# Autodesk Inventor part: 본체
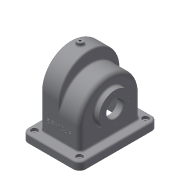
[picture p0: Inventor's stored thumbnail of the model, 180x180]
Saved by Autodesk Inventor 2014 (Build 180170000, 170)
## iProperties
Created: 2017-11
Part Number: 본체
Material: Generic
Document SubType Name: Modeling
Designer: user
Density: 1 g/cm^3
Appearance: Default
Author: user
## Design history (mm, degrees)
sketch "스케치1"
  geometry: L1 (55, -75)-(-55, -75); L2 (-55, -75)-(-55, 75); L3 (-55, 75)-(55, 75); L4 (55, 75)-(55, -75); L5 (55, -75)-(-55, 75); L6 (-55, -75)-(55, 75); 1 further point
  constraints: 12 end point, 2 midpoint, 2 parallel, 1 horizontal, 1 perpendicular
  dimensions: "d0" = 110 distance of L1.start L1.end; "d1" = 150 distance of L1.end L2.end
extrude "돌출1" new body sketch "스케치1" distance "d2" = 15; taper "d3" = 0 deg
sketch "스케치2"
  geometry: L1 (-55, 15)-(55, 15) reference; L2 (-38, 15)-(-38, 138); L3 (-38, 138)-(0, 138); L4 (0, 138)-(0, 115); L5 (0, 115)-(38, 115); L6 (38, 115)-(38, 15); L7 (-55, 0)-(-55, 15) reference; L8 (-38, 15)-(38, 15); L9 (-5, 133)-(-33, 133); L10 (-33, 133)-(-33, 15); L11 (33, 15)-(33, 110); L12 (33, 110)-(-5, 110); L13 (-5, 110)-(-5, 133); 1 further point
  constraints: 22 end point, 4 parallel, 4 perpendicular, 4 point on line, 1 collinear, 1 other
  dimensions: "d4" = 76 horizontal distance of L5.end L2.end; "d5" = 38 distance of L2.end L3.end; "d6" = 55 distance from line of L3.end L7; "d13" = 5 distance between parallel lines of L3 L9; "d102" = 123 distance of L2.end L2.start; "d103" = 100 distance of L5.end L6.end
extrude "돌출2" new body sketch "스케치2" stored distance "d7" = 116; taper "d8" = 0 deg
fillet "모깎기1" dims "d9" = 58
fillet "모깎기2" dims "d10" = 58
fillet "모깎기3" dims "d11" = 3
fillet "모깎기4" dims "d12" = 8
feature "쉘1" dims "d14" = 2
sketch "스케치6"
  geometry: L1 (-30, 56)-(30, 56) reference; L2 (36, 50)-(36, -50) reference; L3 (-36, -50)-(-36, 50) reference; L4 (30, -56)-(-30, -56) reference; A1 r 6 centre (30, 50) between (36, 50) and (30, 56) reference; A2 r 6 centre (-30, 50) between (-30, 56) and (-36, 50) reference; A3 r 6 centre (-30, -50) between (-36, -50) and (-30, -56) reference; A4 r 6 centre (30, -50) between (30, -56) and (36, -50) reference; 1 further point
extrude "돌출3" cut sketch "스케치6" distance "d15" = 15; taper "d16" = 0 deg
fillet "모깎기5" dims "d17" = 12
hole "구멍1" diameter "d20" = 5; stored, may be unused: countersink angle "d24" = 90 deg, drill point angle "d26" = 0 deg; dims "d18" = 10, "d19" = 10, "d21" = 6, "d22" = 12, "d23" = 5, "d25" = 8
hole "구멍2" diameter "d29" = 5; stored, may be unused: countersink angle "d33" = 90 deg, drill point angle "d35" = 0 deg; dims "d27" = 10, "d28" = 10, "d30" = 6, "d31" = 12, "d32" = 5, "d34" = 8
hole "구멍3" diameter "d38" = 5; stored, may be unused: countersink angle "d42" = 90 deg, drill point angle "d44" = 0 deg; dims "d36" = 10, "d37" = 10, "d39" = 6, "d40" = 12, "d41" = 5, "d43" = 8
hole "구멍4" diameter "d47" = 5; stored, may be unused: countersink angle "d51" = 90 deg, drill point angle "d53" = 0 deg; dims "d45" = 10, "d46" = 10, "d48" = 6, "d49" = 12, "d50" = 5, "d52" = 8
fillet "모깎기6" dims "d54" = 3
sketch "스케치8"
  geometry: L1 (13, -15)-(-113, -15) reference; C1 r 31 at (-50, 50); A1 r 50 centre (-50, 42) between (0, 42) and (-100, 42) reference; 1 further point
  constraints: 1 centre point, 1 vertical alignment
  dimensions: "d59" = 65 distance from line of C1.centre L1; "d60" = 62 diameter of C1
extrude "돌출5" join sketch "스케치8" distance "d61" = 10; taper "d62" = 0 deg
fillet "모깎기8" dims "d63" = 3
sketch "스케치9"
  geometry: L1 (113, -15)-(-13, -15) reference; C1 r 37.5 at (50, 50); A1 r 50 centre (50, 65) between (100, 65) and (0, 65) reference; 1 further point
  constraints: 1 centre point, 1 vertical alignment
  dimensions: "d64" = 75 diameter of C1; "d65" = 65 distance from line of L1 C1.centre
extrude "돌출6" join sketch "스케치9" distance "d66" = 9; taper "d67" = 0 deg
fillet "모깎기9" dims "d68" = 3
sketch "스케치10" dims "d69" = 58
  geometry: C1 r 37.5 at (0, 0) reference; 3 further points
  constraints: 2 vertical alignment, 1 coincident, 2 other
hole "구멍5" sketch "스케치10" at (0, 29) diameter "d70" = 2; stored, may be unused: countersink angle "d74" = 82 deg, drill point angle "d76" = 118 deg; dims "d71" = 6, "d72" = 19, "d73" = 5, "d75" = 8
sketch "스케치11" dims "d80" = 52
  geometry: C1 r 31 at (0, 0) reference; 3 further points
  constraints: 2 vertical alignment, 1 coincident, 2 other
hole "구멍6" sketch "스케치11" at (0, 26) diameter "d81" = 2; stored, may be unused: countersink angle "d85" = 82 deg, drill point angle "d87" = 118 deg; dims "d82" = 6, "d83" = 19, "d84" = 5, "d86" = 8
sketch "스케치12"
  geometry: C1 r 37.5 at (0, 0) reference; C2 r 16 at (0, 0); 1 further point
  constraints: 1 centre point, 1 coincident
  dimensions: "d91" = 32 diameter of C2
extrude "돌출7" cut sketch "스케치12" stored distance "d92" = 9; taper "d93" = 0 deg
chamfer "모따기1" distance "d94" = 1; stored, may be unused: second distance "d95" = 2, angle "d96" = 45 deg
node "작업 평면1"
sketch "스케치13"
  geometry: L1 (38, 50)-(38, -50) reference; C1 r 6 at (19, 0); 1 further point
  constraints: 1 centre point, 1 horizontal alignment
  dimensions: "d98" = 12 diameter of C1; "d99" = 19 distance from line of C1.centre L1
extrude "돌출9" join sketch "스케치13" distance "d104" = 9; taper "d105" = 0 deg
fillet "모깎기10" dims "d106" = 3
hole "구멍7" diameter "d109" = 4; stored, may be unused: countersink angle "d113" = 82 deg, drill point angle "d115" = 118 deg; dims "d107" = 10, "d108" = 10, "d110" = 6, "d111" = 19, "d112" = 5, "d114" = 8
sketch "스케치14"
  geometry: L1 (43, 0)-(-43, 0) reference; L2 (-38, 80)-(-38, 15) reference; 2 further points
  constraints: 1 other
  dimensions: "d116" = 40 distance from line of L1 point (0, 40); "d117" = 38 distance from line of point (0, 40) L2
feature "결합1"
  node "솔리드2"
feature "엠보싱1" dims "d9" = 58, "d118" = 0.5, "d119" = 0
fillet "모깎기11" dims "d120" = 3
node "솔리드1"
pattern_circular "원형 패턴1" dims angle "d78" = 360 deg
pattern_circular "원형 패턴2" dims angle "d89" = 360 deg
other parameters: "d97" = 144
